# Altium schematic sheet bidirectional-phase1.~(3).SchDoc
size 431 x 279 mm; Date: Not shown in title block; ApprovedBy: Not shown in title block; CheckedBy: Not shown in title block; Author: Not shown in title block; CompanyName: Not shown in title block; Engineer: Not shown in title block; Organization: Not shown in title block; Address1: Not shown in title block; Address2: Not shown in title block; Address3: Not shown in title block; Address4: Not shown in title block; DocumentNumber: 4; Revision: Use project parameter SCH_Rev; SheetNumber: 4; SheetTotal: 6; PageSetup: Record=PageOptions|CenterHorizontal=True|CenterVertical=True|PrintScale=0.96|XCorrection=1.00|YCorrection=1.00|PrintKind=0|BorderSize=5000000|LeftOffset=0|BottomOffset=0|Orientation=2|PaperLength=1000|PaperWidth=1000|Scale=100|PaperSource=15|PrintQuality=600|MediaType=1|DitherType=10|PaperKind=11x17|PrintScaleMode=1
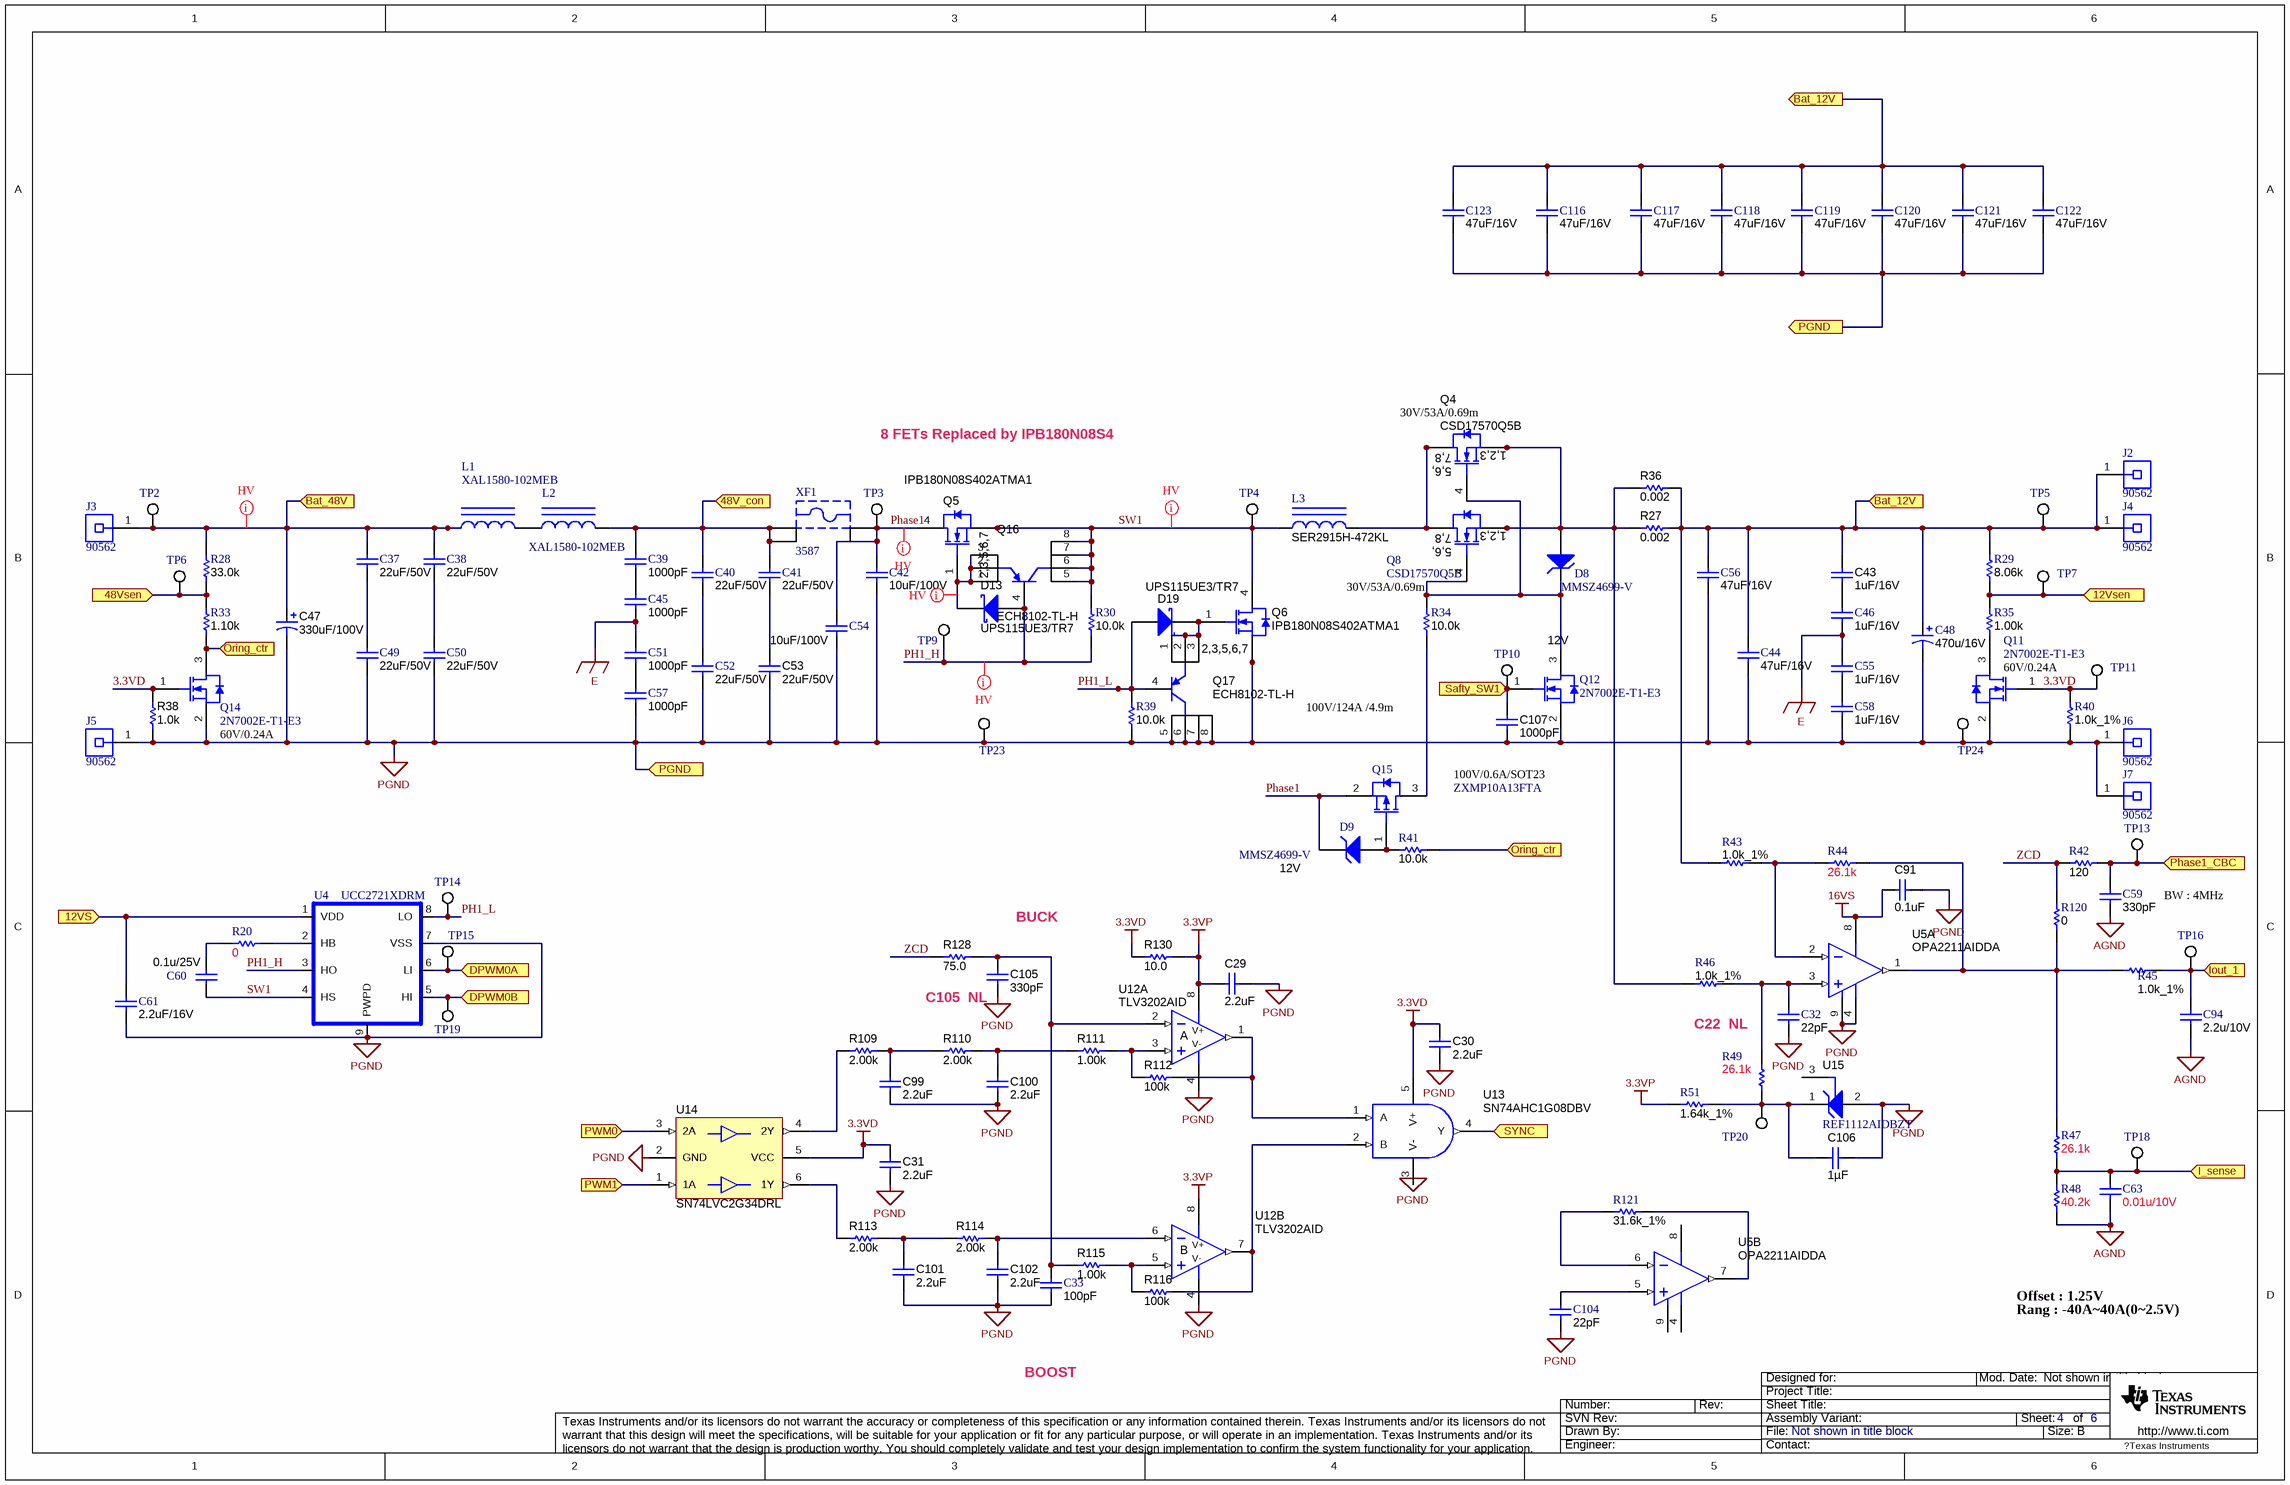
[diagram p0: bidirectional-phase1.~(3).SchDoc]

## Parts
C29  ValueDisplayed: 2.2uF  [0603]  (hidden comment: C0603C225K9PACTU)
C30  ValueDisplayed: 2.2uF  [0603]  (hidden comment: C0603C225K9PACTU)
C31  ValueDisplayed: 2.2uF  [0603]  (hidden comment: C0603C225K9PACTU)
C32  ValueDisplayed: 22pF  [0603]  (hidden comment: 06035A220JAT2A)
C33  ValueDisplayed: 100pF  [0603]  (hidden comment: 06033C101KAT2A)
C37  ValueDisplayed: 22uF/50V  [CKG57N]  (hidden comment: CKG57NX5R1H226M500JH)
C38  ValueDisplayed: 22uF/50V  [CKG57N]  (hidden comment: CKG57NX5R1H226M500JH)
C39  ValueDisplayed: 1000pF  [0603]  (hidden comment: 06031C102JAT2A)
C40  ValueDisplayed: 22uF/50V  [CKG57N]  (hidden comment: CKG57NX5R1H226M500JH)
C41  ValueDisplayed: 22uF/50V  [CKG57N]  (hidden comment: CKG57NX5R1H226M500JH)
C42  ValueDisplayed: 10uF/100V  [2220]  (hidden comment: C5750X7S2A106M)
C43  ValueDisplayed: 1uF/16V  [0805_HV]  (hidden comment: B37941K9105K62)
C44  ValueDisplayed: 47uF/16V  [1210]  (hidden comment: GRM32ER61C476ME15L)
C45  ValueDisplayed: 1000pF  [0603]  (hidden comment: 06031C102JAT2A)
C46  ValueDisplayed: 1uF/16V  [0805_HV]  (hidden comment: B37941K9105K62)
C47  ValueDisplayed: 330uF/100V  [CAPSMT_62_MN0]  (hidden comment: EMVE101GTR331MMN0S)
C48  ValueDisplayed: 470u/16V  [CAPSMT_62_JA0]  (hidden comment: EMVA250ADA471MJA0G)
C49  ValueDisplayed: 22uF/50V  [CKG57N]  (hidden comment: CKG57NX5R1H226M500JH)
C50  ValueDisplayed: 22uF/50V  [CKG57N]  (hidden comment: CKG57NX5R1H226M500JH)
C51  ValueDisplayed: 1000pF  [0603]  (hidden comment: 06031C102JAT2A)
C52  ValueDisplayed: 22uF/50V  [CKG57N]  (hidden comment: CKG57NX5R1H226M500JH)
C53  ValueDisplayed: 22uF/50V  [CKG57N]  (hidden comment: CKG57NX5R1H226M500JH)
C54  ValueDisplayed: 10uF/100V  [2220]  (hidden comment: C5750X7S2A106M)
C55  ValueDisplayed: 1uF/16V  [0805_HV]  (hidden comment: B37941K9105K62)
C56  ValueDisplayed: 47uF/16V  [1210]  (hidden comment: GRM32ER61C476ME15L)
C57  ValueDisplayed: 1000pF  [0603]  (hidden comment: 06031C102JAT2A)
C58  ValueDisplayed: 1uF/16V  [0805_HV]  (hidden comment: B37941K9105K62)
C59  ValueDisplayed: 330pF  [0603]  (hidden comment: 06035A331JAT2A)
C60  ValueDisplayed: 0.1u/25V  [0603]  (hidden comment: 06033C104KAT2A)
C61  ValueDisplayed: 2.2uF/16V  [0805_HV]  (hidden comment: 0805YD225KAT2A)
C63  ValueDisplayed: 0.01u/10V  [0603]  (hidden comment: 06031C103JAT2A)
C91  ValueDisplayed: 0.1uF  [0603]  (hidden comment: 06033C104JAT2A)
C94  ValueDisplayed: 2.2u/10V  [0603]  (hidden comment: C0603C225K8PACTU)
C99  ValueDisplayed: 2.2uF  [0805_HV]  (hidden comment: 0805YD225KAT2A)
C100  ValueDisplayed: 2.2uF  [0805_HV]  (hidden comment: 0805YD225KAT2A)
C101  ValueDisplayed: 2.2uF  [0805_HV]  (hidden comment: 0805YD225KAT2A)
C102  ValueDisplayed: 2.2uF  [0805_HV]  (hidden comment: 0805YD225KAT2A)
C104  ValueDisplayed: 22pF  [0603]  (hidden comment: 06035A220JAT2A)
C105  ValueDisplayed: 330pF  [0603]  (hidden comment: 06031C331JAT2A)
C106  ValueDisplayed: 1µF  [0603_095]  (hidden comment: C0603C105K3RACTU)
C107  ValueDisplayed: 1000pF  [0603]  (hidden comment: C0603X102K5RACTU)
C116  ValueDisplayed: 47uF/16V  [1210]  (hidden comment: GRM32ER61C476ME15L)
C117  ValueDisplayed: 47uF/16V  [1210]  (hidden comment: GRM32ER61C476ME15L)
C118  ValueDisplayed: 47uF/16V  [1210]  (hidden comment: GRM32ER61C476ME15L)
C119  ValueDisplayed: 47uF/16V  [1210]  (hidden comment: GRM32ER61C476ME15L)
C120  ValueDisplayed: 47uF/16V  [1210]  (hidden comment: GRM32ER61C476ME15L)
C121  ValueDisplayed: 47uF/16V  [1210]  (hidden comment: GRM32ER61C476ME15L)
C122  ValueDisplayed: 47uF/16V  [1210]  (hidden comment: GRM32ER61C476ME15L)
C123  ValueDisplayed: 47uF/16V  [1210]  (hidden comment: GRM32ER61C476ME15L)
D8  MMSZ4699-V  value 12V  [SOD-123]
D9  MMSZ4699-V  value 12V  [SOD-123]
D13  UPS115UE3/TR7  [DO-216AA]
D19  UPS115UE3/TR7  [DO-216AA]
J2  90562  [Morris_90562]
J3  90562  [Morris_90562]
J4  90562  [Morris_90562]
J5  90562  [Morris_90562]
J6  90562  [Morris_90562]
J7  90562  [Morris_90562]
L1  XAL1580-102MEB  [XAL1580]
L2  XAL1580-102MEB  [XAL1580]
L3  SER2915H-472KL  [SER2915H]
Q4  CSD17570Q5B  [TRANS_NexFET_Q5B]
Q5  IPB180N08S402ATMA1  [DDPAK-7]
Q6  IPB180N08S402ATMA1  [DDPAK-7]
Q8  CSD17570Q5B  [TRANS_NexFET_Q5B]
Q11  2N7002E-T1-E3  [SOT-23]
Q12  2N7002E-T1-E3  [SOT-23]
Q14  2N7002E-T1-E3  [SOT-23]
Q15  ZXMP10A13FTA  [SOT-23]
Q16  ECH8102-TL-H  [ECH8]
Q17  ECH8102-TL-H  [ECH8]
R20  value 0  [0603]  (hidden comment: MCR03EZPJ000)
R27  ValueDisplayed: 0.002  [2512]  (hidden comment: ERJ-M1WTF2M0U)
R28  ValueDisplayed: 33.0k  [0603]  (hidden comment: CRCW060333K0FKEA)
R29  ValueDisplayed: 8.06k  [0603]  (hidden comment: CRCW06038K06FKEA)
R30  value 10.0k  [0603]  (hidden comment: RG1608P-103-B-T5)
R33  ValueDisplayed: 1.10k  [0603]  (hidden comment: RC0603FR-071K1L)
R34  ValueDisplayed: 10.0k  [0603]  (hidden comment: CRCW060310K0FKEA)
R35  ValueDisplayed: 1.00k  [0603]  (hidden comment: CRCW06031K00FKEA)
R36  ValueDisplayed: 0.002  [2512]  (hidden comment: ERJ-M1WTF2M0U)
R38  value 1.0k  [0603]  (hidden comment: CRCW06031K00JNEA)
R39  value 10.0k  [0603]  (hidden comment: RG1608P-103-B-T5)
R40  value 1.0k_1%  [0603]  (hidden comment: CRCW06031K00JNEA)
R41  ValueDisplayed: 10.0k  [0603]  (hidden comment: CRCW060310K0FKEA)
R42  ValueDisplayed: 120  [0603]  (hidden comment: CRCW0603120RJNEA)
R43  value 1.0k_1%  [0603]  (hidden comment: CRCW06031K00JNEA)
R44  value 26.1k  [0603]  (hidden comment: CRCW060326K1FKEA)
R45  value 1.0k_1%  [0603]  (hidden comment: CRCW06031K00JNEA)
R46  value 1.0k_1%  [0603]  (hidden comment: CRCW06031K00JNEA)
R47  value 26.1k  [0603]  (hidden comment: CRCW060326K1FKEA)
R48  value 40.2k  [0603]  (hidden comment: CRCW060340K2FKEA)
R49  value 26.1k  [0603]  (hidden comment: CRCW060326K1FKEA)
R51  value 1.64k_1%  [0603]  (hidden comment: CRCW06031K65FKEA)
R109  value 2.00k  [0603]  (hidden comment: CRCW06032K00FKEA)
R110  value 2.00k  [0603]  (hidden comment: CRCW06032K00FKEA)
R111  value 1.00k  [0603]  (hidden comment: CRCW06031K00FKEA)
R112  ValueDisplayed: 100k  [0603]  (hidden comment: CRCW0603100KJNEA)
R113  value 2.00k  [0603]  (hidden comment: CRCW06032K00FKEA)
R114  value 2.00k  [0603]  (hidden comment: CRCW06032K00FKEA)
R115  value 1.00k  [0603]  (hidden comment: CRCW06031K00FKEA)
R116  ValueDisplayed: 100k  [0603]  (hidden comment: CRCW0603100KJNEA)
R120  value 0  [0603]  (hidden comment: ERJ-3GEY0R00V)
R121  value 31.6k_1%  [0603]  (hidden comment: CRCW060331K6FKEA)
R128  ValueDisplayed: 75.0  [0603]  (hidden comment: CRCW060375R0FKEA)
R130  value 10.0  [0603]  (hidden comment: CRCW060310R0FKEA)
TP2  5002  [Keystone5002]  (value not drawn)
TP3  5016  [Testpoint_Keystone_Compact]  (value not drawn)
TP4  5002  [Keystone5002]  (value not drawn)
TP5  5002  [Keystone5002]  (value not drawn)
TP6  5002  [Keystone5002]  (value not drawn)
TP7  5002  [Keystone5002]  (value not drawn)
TP9  5002  [Keystone5002]  (value not drawn)
TP10  5002  [Keystone5002]  (value not drawn)
TP11  5002  [Keystone5002]  (value not drawn)
TP13  5002  [Keystone5002]  (value not drawn)
TP14  5002  [Keystone5002]  (value not drawn)
TP15  5002  [Keystone5002]  (value not drawn)
TP16  5002  [Keystone5002]  (value not drawn)
TP18  5002  [Keystone5002]  (value not drawn)
TP19  5002  [Keystone5002]  (value not drawn)
TP20  5002  [Keystone5002]  (value not drawn)
TP23  5002  [Keystone5002]  (value not drawn)
TP24  5002  [Keystone5002]  (value not drawn)
U4  UCC2721XDRM  [DRM0008A]
U5  OPA2211AIDDA  [DDA0008C_N]  (parts A,B of 2)
U12  TLV3202AID  [D0008A_L]  (parts A,B of 2)
U13  SN74AHC1G08DBV  [DBV0005A_N]
U14  SN74LVC2G34DRL  [DRL0006A_N]
U15  REF1112AIDBZT  [DBZ0003A_N]
XF1  3587  [KEYSTONE_3587]

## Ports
12VS, 12Vsen, 48V_con, 48Vsen, Bat_12V, Bat_48V, DPWM0A, DPWM0B, I_sense, Iout_1, Oring_ctr, PGND, Phase1_CBC, PWM0, PWM1, Safty_SW1, SYNC

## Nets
3.3VD: C30.1 C31.2 Q11.1(G) Q14.1(G) R38.2 R40.2 R130.2 TP11.1 U13.5(V+) U14.5(VCC)
3.3VP: C29.2 R51.1 R130.1 U12.8(V+)
16VS: C91.1 U5.8(V+)
AGND: C59.2 C63.2 C94.2 R48.1
E: C45.2 C46.2 C51.1 C55.1
PGND: C29.1 C30.2 C31.1 C32.2 C33.2 C42.2 C44.2 C47.2(-) C48.2(-) C49.2 C50.2 C52.2 C53.2 C54.2 C56.2 C57.2 C58.2 C61.2 C91.2 C99.2 C100.2 C101.2 C102.2 C104.2 C105.2 C106.1 C107.2 C116.2 C117.2 C118.2 C119.2 C120.2 C121.2 C122.2 C123.2 J5.1 J6.1 J7.1 Q6.2(S) Q6.3(S) Q6.5(S) Q6.6(S) Q6.7(S) Q11.2(S) Q12.2(S) Q14.2(S) Q17.5(C) Q17.6(C) Q17.7(C) Q17.8(C) R38.1 R39.1 R40.1 TP23.1 TP24.1 U4.7(VSS) U4.9(PWPD) U5.4(V-) U5.9(EP) U12.4(V-) U14.2(GND) U15.2(GND) ; port PGND
12VS: C61.1 U4.1(VDD) ; port 12VS
12Vsen: R29.1 R35.2 TP7.1 ; port 12Vsen
48V_con: C39.1 C40.1 C41.1 L2.2 XF1.1 XF1.2 ; port 48V_con
48Vsen: R28.1 R33.2 TP6.1 ; port 48Vsen
Bat_12V: C43.1 C44.1 C48.1(+) C56.1 C116.1 C117.1 C118.1 C119.1 C120.1 C121.1 C122.1 C123.1 J2.1 J4.1 R27.2 R29.2 R36.2 R43.1 TP5.1 ; port Bat_12V
Bat_48V: C37.1 C38.1 C47.1(+) J3.1 L1.1 R28.2 TP2.1 ; port Bat_48V
DPWM0A: TP15.1 U4.6(LI) ; port DPWM0A
DPWM0B: TP19.1 U4.5(HI) ; port DPWM0B
I_sense: C63.1 R47.1 R48.2 TP18.1 ; port I_sense
Iout_1: C94.1 R45.2 TP16.1 ; port Iout_1
Oring_ctr: Q14.3(D) R33.1 R41.1 ; port Oring_ctr
PH1_H: D13.2(A) Q16.4(B) R30.1 TP9.1 U4.3(HO)
PH1_L: D19.2(A) Q17.4(B) R39.2 TP14.1 U4.8(LO)
Phase1: C42.1 C54.1 D9.1(K) Q5.4(D) Q15.2(S) TP3.1 XF1.3 XF1.4
Phase1_CBC: C59.1 R42.2 TP13.1 ; port Phase1_CBC
PWM0: U14.3(2A) ; port PWM0
PWM1: U14.1(1A) ; port PWM1
Safty_SW1: C107.1 Q12.1(G) TP10.1 ; port Safty_SW1
SW1: C60.2 L3.1 Q5.2(S) Q5.3(S) Q5.5(S) Q5.6(S) Q5.7(S) Q6.4(D) Q16.5(C) Q16.6(C) Q16.7(C) Q16.8(C) R30.2 TP4.1 U4.4(HS)
SYNC: U13.4(Y) ; port SYNC
ZCD: R42.1 R120.2 R128.1
NetC32_1: C32.1 R46.2 R49.2 U5.3(IN_A+)
NetC33_1: C33.1 C105.1 R115.1 R128.2 U12.2(IN-)
NetC37_2: C37.2 C49.1
NetC38_2: C38.2 C50.1
NetC39_2: C39.2 C45.1
NetC40_2: C40.2 C52.1
NetC41_2: C41.2 C53.1
NetC43_2: C43.2 C46.1
NetC51_2: C51.2 C57.1
NetC55_2: C55.2 C58.1
NetC60_1: C60.1 R20.1
NetC99_1: C99.1 R109.2 R110.1
NetC100_1: C100.1 R110.2 R111.1
NetC101_1: C101.1 R113.2 R114.1
NetC102_1: C102.1 R114.2 U12.6(IN-)
NetC104_1: C104.1 U5.5(IN_B+)
NetC106_2: C106.2 R49.1 R51.2 TP20.1 U15.1(VO)
NetD8_1: D8.1(K) Q4.4(G) Q8.4(G) Q12.3(D) R34.2
NetD8_2: D8.2(A) Q4.1(S) Q4.2(S) Q4.3(S) Q8.1(S) Q8.2(S) Q8.3(S) R27.1 R36.1 R46.1
NetD9_2: D9.2(A) Q15.1(G) R41.2
NetD13_1: D13.1(K) Q5.1(G) Q16.1(E) Q16.2(E) Q16.3(E)
NetD19_1: D19.1(K) Q6.1(G) Q17.1(E) Q17.2(E) Q17.3(E)
NetL1_2: L1.2 L2.1
NetL3_2: L3.2 Q4.5(D) Q4.6(D) Q4.7(D) Q4.8(D) Q8.5(D) Q8.6(D) Q8.7(D) Q8.8(D)
NetQ11_3: Q11.3(D) R35.1
NetQ15_3: Q15.3(D) R34.1
NetR20_2: R20.2 U4.2(HB)
NetR43_2: R43.2 R44.1 U5.2(IN_A-)
NetR44_2: R44.2 R45.1 R47.2 R120.1 U5.1(OUT_A)
NetR109_1: R109.1 U14.4(2Y)
NetR111_2: R111.2 R112.2 U12.3(IN+)
NetR112_1: R112.1 U12.1(OUT) U13.1(A)
NetR113_1: R113.1 U14.6(1Y)
NetR115_2: R115.2 R116.2 U12.5(IN+)
NetR116_1: R116.1 U12.7(OUT) U13.2(B)
NetR121_1: R121.1 U5.6(IN_B-)
NetR121_2: R121.2 U5.7(OUT_B)

Not connected (* = marked no-connect by the designer): U13 3(V-); U15 3(NC)

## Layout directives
net class HV: Bat_48V, NetD13_1, PH1_H, Phase1, SW1

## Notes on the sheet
- 8 FETs Replaced by IPB180N08S4
- (near Q4) 30V/53A/0.69m
- (near R34) 30V/53A/0.69m
- (near Q11) 60V/0.24A
- (near Q14) 60V/0.24A
- 100V/124A /4.9m
- 100V/0.6A/SOT23
- BW : 4MHz
- BUCK
- (near C105) C105  NL
- C22  NL
- Offset : 1.25V
- BOOST
- Rang : -40A~40A(0|.5V)
- Labels drawn without touching a wire or pin: PGND

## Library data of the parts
C29-C31 = C0603C225K9PACTU: CAP, CERM, 2.2uF, 6.3V, +/-10%, X5R, 0603; Manufacturer: Kemet; Polarized: N; CompType: Capacitor; U/M: EA; Cap_F: 0.0000022; Tolerance_%: 10; Value1: Unknown; VDC_V: 6.3; TaMin_C: -55; TaMax_C: 85
C32 C104 = 06035A220JAT2A: CAP, CERM, 22pF, 50V, +/-5%, C0G/NP0, 0603; Manufacturer: AVX; Polarized: N; CompType: Capacitor; U/M: EA; Cap_F: 0.000000000022; Tolerance_%: 5; ESR_Ohm: 0.259; Value1: 0.259 ohm; VDC_V: 50; TaMin_C: -55; TaMax_C: 125
C33 = 06033C101KAT2A: CAP, CERM, 100pF, 25V, +/-10%, X7R, 0603; Manufacturer: AVX; Polarized: N; CompType: Capacitor; U/M: EA; Cap_F: 0.0000000001; Tolerance_%: 10; Value1: Unknown; VDC_V: 25; TaMin_C: -55; TaMax_C: 125
C37 C38 C40 C41 C49 C50 C52 C53 = CKG57NX5R1H226M500JH: CAP, CERM, 22uF, 50V, +/-20%, X5R, 6x5x5mm; Manufacturer: TDK; Polarized: N; CompType: Capacitor; U/M: EA; Cap_F: 0.000022; Tolerance_%: 20; Value1: Unknown; VDC_V: 50; TaMin_C: -55; TaMax_C: 85; Cap_Case: 2220
C39 C45 C51 C57 = 06031C102JAT2A: CAP, CERM, 1000pF, 100V, +/-5%, X7R, 0603; Manufacturer: AVX; Polarized: N; CompType: Capacitor; U/M: EA; Cap_F: 0.000000001; Tolerance_%: 5; ESR_Ohm: 0.276; Value1: 0.276 ohm; VDC_V: 100; TaMin_C: -55; TaMax_C: 125
C42 C54 = C5750X7S2A106M: CAP, CERM, 10uF, 100V, +/-20%, X7S, 2220; Manufacturer: TDK; Polarized: N; CompType: Capacitor; U/M: EA; Cap_F: 0.00001; Tolerance_%: 20; ESR_Ohm: 0.005; Value1: 0.005 ohm; VDC_V: 100; IRMS_A: 6.45; TaMin_C: -55; TaMax_C: 125
C43 C46 C55 C58 = B37941K9105K62: CAP, CERM, 1uF, 16V, +/-10%, X7R, 0805; Manufacturer: EPCOS Inc; Polarized: N; CompType: Capacitor; U/M: EA; Cap_F: 0.000001; Tolerance_%: 10; Value1: Unknown; VDC_V: 16; TaMin_C: -55; TaMax_C: 125; Cap_Case: 0805
C44 C56 C116-C123 = GRM32ER61C476ME15L: CAP, CERM, 47uF, 16V, +/-20%, X5R, 1210; Manufacturer: MuRata; Polarized: N; CompType: Capacitor; U/M: EA; Cap_F: 0.000047; Tolerance_%: 20; ESR_Ohm: 0.002; Value1: 0.002 ohm; VDC_V: 16; TaMin_C: -55; TaMax_C: 85
C47 = EMVE101GTR331MMN0S: CAP, AL, 330uF, 100V, +/-20%,  ohm, SMD; Manufacturer: Nippon Chemi-Con; Polarized: Y; CompType: Capacitor; U/M: EA; Cap_F: 0.00033; Tolerance_%: 20; Value1: Unknown; VDC_V: 100; IRMS_A: 0.98; TaMin_C: -40; TaMax_C: 105; Cap_Case: MN0
C48 = EMVA250ADA471MJA0G: CAP, AL, 470uF, 25V, +/-20%,  ohm, SMD; Manufacturer: Nippon Chemi-Con; Polarized: Y; CompType: Capacitor; U/M: EA; Cap_F: 0.00047; Tolerance_%: 20; Value1: Unknown; VDC_V: 25; IRMS_A: 0.4; TaMin_C: -40; TaMax_C: 85; Cap_Case: JA0
C59 = 06035A331JAT2A: CAP, CERM, 330pF, 50V, +/-5%, C0G/NP0, 0603; Manufacturer: AVX; Polarized: N; CompType: Capacitor; U/M: EA; Cap_F: 0.00000000033; Tolerance_%: 5; ESR_Ohm: 0.071; Value1: 0.071 ohm; VDC_V: 50; TaMin_C: -55; TaMax_C: 125
C60 = 06033C104KAT2A: CAP, CERM, 0.1uF, 25V, +/-10%, X7R, 0603; Manufacturer: AVX; Polarized: N; CompType: Capacitor; U/M: EA; Cap_F: 0.0000001; Tolerance_%: 10; ESR_Ohm: 0.05; Value1: 0.05 ohm; VDC_V: 25; TaMin_C: -55; TaMax_C: 125
C61 C99-C102 = 0805YD225KAT2A: CAP, CERM, 2.2uF, 16V, +/-10%, X5R, 0805; Manufacturer: AVX; Polarized: N; CompType: Capacitor; U/M: EA; Cap_F: 0.0000022; Tolerance_%: 10; ESR_Ohm: 0.009; Value1: 0.009 ohm; VDC_V: 16; TaMin_C: -55; TaMax_C: 85; Cap_Case: 0805
C63 = 06031C103JAT2A: CAP, CERM, 0.01uF, 100V, +/-5%, X7R, 0603; Manufacturer: AVX; Polarized: N; CompType: Capacitor; U/M: EA; Cap_F: 0.00000001; Tolerance_%: 5; ESR_Ohm: 0.098; Value1: 0.098 ohm; VDC_V: 100; TaMin_C: -55; TaMax_C: 125
C91 = 06033C104JAT2A: CAP, CERM, 0.1uF, 25V, +/-5%, X7R, 0603; Manufacturer: AVX; Polarized: N; CompType: Capacitor; U/M: EA; Cap_F: 0.0000001; Tolerance_%: 5; ESR_Ohm: 0.05; Value1: 0.05 ohm; VDC_V: 25; TaMin_C: -55; TaMax_C: 125
C94 = C0603C225K8PACTU: CAP, CERM, 2.2uF, 10V, +/-10%, X5R, 0603; Manufacturer: Kemet; Polarized: N; CompType: Capacitor; U/M: EA; Cap_F: 0.0000022; Tolerance_%: 10; Value1: Unknown; TaMin_C: -55; TaMax_C: 85
C105 = 06031C331JAT2A: CAP, CERM, 330pF, 100V, +/-5%, X7R, 0603; Manufacturer: AVX; Polarized: N; CompType: Capacitor; U/M: EA; Cap_F: 0.00000000033; Tolerance_%: 5; ESR_Ohm: 0.472; Value1: 0.472 ohm; VDC_V: 100; TaMin_C: -55; TaMax_C: 125
C106 = C0603C105K3RACTU: CAP, CERM, 1 µF, 25 V, +/- 10%, X7R, 0603_095; Manufacturer: Kemet; Polarized: N; CompType: Capacitor; Value: 1uF; U/M: EA; Cap_F: 0.000001; Tolerance_%: 10; Value1: Unknown; VDC_V: 25; Value2: 25V; TaMin_C: -55; TaMax_C: 125; Cap_Case: 0603
C107 = C0603X102K5RACTU: CAP, CERM, 1000 pF, 50 V, +/- 10%, X7R, 0603; Manufacturer: Kemet; Polarized: N; CompType: Capacitor; Value: 1000pF; U/M: EA; Cap_F: 0.000000001; Tolerance_%: 10; Value1: Unknown; VDC_V: 50; Value2: 50V; TaMin_C: -55; TaMax_C: 125
D8 D9 = MMSZ4699-V: Diode, Zener, 12V, 500mW, SOD-123; Manufacturer: Vishay-Semiconductor; SymbolCreator: a0412235; U/M: EA; Power_W: 0.5; Vz_V: 12; Value1: 0.5W; RJA_CperW: 67
D13 D19 = UPS115UE3/TR7: Diode, Schottky, 15 V, 1 A, DO-216-AA; Manufacturer: Microsemi; U/M: EA; Vf_V: 0.31; Value: 15V; Value1: 1A; Value2: 0.31V; Io_A: 1; Vr_V: 15; TJmax_C: 100
J2-J7 = 90562: Connector Lug, wire range #6 - 4/0, 600V; Manufacturer: Morris Products; SymbolCreator: a0799628; CompType: Receptacle; U/M: EA
L1 L2 = XAL1580-102MEB: Inductor, Shielded, Composite, 1uH, 57.5A, 0.000929 ohm, SMD; Manufacturer: Coilcraft; Ind_H: 1.0E-6; ValueDisplayed: 1µH; Imax_A: 57.5; Irms: 57.5A @ 40C rise; Isat: 73.5A @ 0.7% inductance drop; U/M: EA
L3 = SER2915H-472KL: Inductor, Shielded E Core, Ferrite, 4.7 µH, 30 A, 0.00186 ohm, SMD; Manufacturer: Coilcraft; Value: 4.7uH; Ind_H: 4.7E-6; ValueDisplayed: 4.7µH; Imax_A: 30; Irms: 30A @ 40C rise; Isat: 50.1A @ 30% inductance drop; Value2: 30A
Q4 Q8 = CSD17570Q5B: MOSFET, N-CH, 30V, 51A, SON 5x6mm; Manufacturer: Texas Instruments; Alternate Manufacturer: None; U/M: EA; ChType: N; VdsMax_V: 30; Value1: 0.0076 ohm; Rdson45_Ohm: 0.0076; Value2: 97 nC; QgTyp_nC: 97; Vgs_V: 20; IdsMax_A: 51
Q5 Q6 = IPB180N08S402ATMA1: MOSFET, N-CH, 80 V, 180 A, DDPAK-7; Manufacturer: Infineon Technologies; Alternate Manufacturer: None; SymbolCreator: a0412235; U/M: EA; ChType: N; Value: 80V; VdsMax_V: 80; Value1: ? ohm; Value2: 128 nC; QgTyp_nC: 128; Vgs_V: 20; IdsMax_A: 180
Q11 Q12 Q14 = 2N7002E-T1-E3: MOSFET, N-CH, 60V, 0.24A, SOT-23; Manufacturer: Vishay-Siliconix; Alternate Manufacturer: None; U/M: EA; ChType: N; VdsMax_V: 60; Value1: 1.8 ohm; Rdson45_Ohm: 1.8; Value2: 0.4 nC; QgTyp_nC: 0.4; Vgs_V: 20; IdsMax_A: 0.24
Q15 = ZXMP10A13FTA: MOSFET, P-CH, -100V, -0.6A, SOT-23; Manufacturer: Diodes Inc.; Alternate Manufacturer: None; U/M: EA; ChType: P; VdsMax_V: -100; Value1: 1 ohm; Rdson45_Ohm: 1; Value2: 3.5 nC; QgTyp_nC: 3.5; Vgs_V: -4; IdsMax_A: -0.6
Q16 Q17 = ECH8102-TL-H, ON Semiconductor: Transistor, PNP, 30 V, 12 A, SMD-8; CompType: BJT; PNP: 1; NPN: 0; Vceo_V: 30; Vcesat1_V: 0.08; Value: 30 V; IcRated_A: 12; Value1: 12 A; HfeMax: 560; TaMin_C: -55; TaMax_C: 150; U/M: EA
R20 = MCR03EZPJ000: RES, 0 ohm, 5%, 0.1W, 0603; Manufacturer: Rohm; CompType: Resistor; Value_Code: 0000; Tolerance_%: 5; Power_W: 0.1; VDC_V: 50; TempCo: 400 ppm/C; EIA_Code: E24; U/M: EA
R27 R36 = ERJ-M1WTF2M0U: RES, 0.002, 1%, 1 W, 2512; Manufacturer: Panasonic; CompType: Resistor; Value: 0.002; Value_Code: 2L000; Tolerance_%: 1; Value2: 1W; TempCo: ppm/C; U/M: EA
R28 = CRCW060333K0FKEA: RES, 33.0 k, 1%, 0.1 W, 0603; Manufacturer: Vishay-Dale; CompType: Resistor; Value: 33.0k; Res_ohm: 33000; Value_Code: 33k0; Tolerance_%: 1; Power_W: 0.1; Value2: 0.1W; VDC_V: 75; TempCo: 100 ppm/C; U/M: EA
R29 = CRCW06038K06FKEA: RES, 8.06 k, 1%, 0.1 W, 0603; Manufacturer: Vishay-Dale; CompType: Resistor; Value: 8.06k; Res_ohm: 8060; Value_Code: 8k06; Tolerance_%: 1; Power_W: 0.1; Value2: 0.1W; VDC_V: 75; TempCo: 100 ppm/C; EIA_Code: E96; U/M: EA
R30 R39 = RG1608P-103-B-T5: RES, 10.0k ohm, 0.1%, 0.1W, 0603; Manufacturer: Susumu Co Ltd; CompType: Resistor; Res_ohm: 10000; Value_Code: 10k0; Tolerance_%: 0.1; VDC_V: 75; TempCo: 25 ppm/C; EIA_Code: E192; U/M: EA
R33 = RC0603FR-071K1L: RES, 1.10 k, 1%, 0.1 W, 0603; Manufacturer: Yageo America; CompType: Resistor; Value: 1.10k; Res_ohm: 1100; Value_Code: 1k10; Tolerance_%: 1; Power_W: 0.1; Value2: 0.1W; VDC_V: 150; TempCo: 200 ppm/C; EIA_Code: E96; U/M: EA
R34 R41 = CRCW060310K0FKEA: RES, 10.0 k, 1%, 0.1 W, 0603; Manufacturer: Vishay-Dale; CompType: Resistor; Value: 10.0k; Res_ohm: 10000; Value_Code: 10k0; Tolerance_%: 1; Power_W: 0.1; Value2: 0.1W; VDC_V: 75; TempCo: 100 ppm/C; EIA_Code: E96; U/M: EA
R35 = CRCW06031K00FKEA: RES, 1.00 k, 1%, 0.1 W, 0603; Manufacturer: Vishay-Dale; CompType: Resistor; Value: 1.00k; Res_ohm: 1000; Value_Code: 1k00; Tolerance_%: 1; Power_W: 0.1; Value2: 0.1W; VDC_V: 75; TempCo: 100 ppm/C; EIA_Code: E96; U/M: EA
R38 R40 R43 R45 R46 = CRCW06031K00JNEA: RES, 1.0k ohm, 5%, 0.1W, 0603; Manufacturer: Vishay-Dale; CompType: Resistor; Res_ohm: 1000; Value_Code: 1k00; Tolerance_%: 5; Power_W: 0.1; VDC_V: 75; TempCo: 200 ppm/C; EIA_Code: E24; U/M: EA
R42 = CRCW0603120RJNEA: RES, 120, 5%, 0.1 W, 0603; Manufacturer: Vishay-Dale; CompType: Resistor; Value: 120; Value_Code: 120R; Tolerance_%: 5; Power_W: 0.1; Value2: 0.1W; VDC_V: 75; TempCo: 200 ppm/C; EIA_Code: E24; U/M: EA
R44 R47 R49 = CRCW060326K1FKEA: RES, 26.1k ohm, 1%, 0.1W, 0603; Manufacturer: Vishay-Dale; CompType: Resistor; Res_ohm: 26100; Value_Code: 26k1; Tolerance_%: 1; Power_W: 0.1; VDC_V: 75; TempCo: 100 ppm/C; EIA_Code: E96; U/M: EA
R48 = CRCW060340K2FKEA: RES, 40.2k ohm, 1%, 0.1W, 0603; Manufacturer: Vishay-Dale; CompType: Resistor; Res_ohm: 40200; Value_Code: 40k2; Tolerance_%: 1; Power_W: 0.1; VDC_V: 75; TempCo: 100 ppm/C; EIA_Code: E96; U/M: EA
R51 = CRCW06031K65FKEA: RES, 1.65k ohm, 1%, 0.1W, 0603; Manufacturer: Vishay-Dale; CompType: Resistor; Res_ohm: 1650; Value_Code: 1k65; Tolerance_%: 1; Power_W: 0.1; VDC_V: 75; TempCo: 100 ppm/C; EIA_Code: E96; U/M: EA
R109 R110 R113 R114 = CRCW06032K00FKEA: RES, 2.00k ohm, 1%, 0.1W, 0603; Manufacturer: Vishay-Dale; CompType: Resistor; Res_ohm: 2000; Value_Code: 2k00; Tolerance_%: 1; Power_W: 0.1; VDC_V: 75; TempCo: 100 ppm/C; EIA_Code: E96; U/M: EA
R111 R115 = CRCW06031K00FKEA: RES, 1.00k ohm, 1%, 0.1W, 0603; Manufacturer: Vishay-Dale; CompType: Resistor; Res_ohm: 1000; Value_Code: 1k00; Tolerance_%: 1; Power_W: 0.1; VDC_V: 75; TempCo: 100 ppm/C; EIA_Code: E96; U/M: EA
R112 R116 = CRCW0603100KJNEA: RES, 100 k, 5%, 0.1 W, 0603; Manufacturer: Vishay-Dale; CompType: Resistor; Value: 100k; Res_ohm: 100000; Tolerance_%: 5; Power_W: 0.1; Value2: 0.1W; VDC_V: 75; TempCo: 200 ppm/C; EIA_Code: E24; U/M: EA
R120 = ERJ-3GEY0R00V: RES, 0 ohm, 5%, 0.1W, 0603; Manufacturer: Panasonic; CompType: Resistor; Value_Code: 0000; Tolerance_%: 5; Power_W: 0.1; VDC_V: 50; TempCo: 600 ppm/C; EIA_Code: E24; U/M: EA
R121 = CRCW060331K6FKEA: RES, 31.6k ohm, 1%, 0.1W, 0603; Manufacturer: Vishay-Dale; CompType: Resistor; Res_ohm: 31600; Value_Code: 31k6; Tolerance_%: 1; Power_W: 0.1; VDC_V: 75; TempCo: 100 ppm/C; EIA_Code: E96; U/M: EA
R128 = CRCW060375R0FKEA: RES, 75.0, 1%, 0.1 W, 0603; Manufacturer: Vishay-Dale; CompType: Resistor; Value: 75.0; Res_ohm: 75; Value_Code: 75R0; Tolerance_%: 1; Power_W: 0.1; Value2: 0.1W; TempCo: 100 ppm/C; EIA_Code: E96; U/M: EA
R130 = CRCW060310R0FKEA: RES, 10.0 ohm, 1%, 0.1W, 0603; Manufacturer: Vishay-Dale; CompType: Resistor; Res_ohm: 10; Value_Code: 10R0; Tolerance_%: 1; Power_W: 0.1; VDC_V: 75; TempCo: 100 ppm/C; EIA_Code: E96; U/M: EA
TP2 TP4-TP7 TP9-TP11 TP13-TP16 TP18-TP20 TP23 TP24 = 5002: Test Point, Miniature, White, TH; Manufacturer: Keystone; CompType: Test Point Loop; U/M: EA
TP3 = 5016: Test Point, Compact, SMT; Manufacturer: Keystone; CompType: Test Point Loop; U/M: EA
U4 = UCC2721XDRM: IC, 120V Boot, 4A Peak, High Frequency High-Side Low-Side Driver; Manufacturer: TI; Alternate Manufacturer: None; Area: 41800
U5 = OPA2211AIDDA: 1.1 nV/rtHz Noise, Low Power, Precision Operational Amplifier, 4.5 to 36 V, -40 to 125 degC, 8-pin SOP (DDA0008C), Green (RoHS & no Sb/Br); Manufacturer: Texas Instruments; Alternate PartNumber: Equivalent; CMRR(Min)(dB): 114; GBW(Typ)(MHz): 45; IIB(Max)(pA): 175000; Iq per channel(Max)(mA): 4.5; Number of Channels: 2; Offset Drift(Typ)(uV/C): 0.35; Packing: TUBE; Rating: Catalog; Slew Rate(Typ)(V/us): 27; Sub Family: High Supply Voltage Amplifier (>=30V), Low Noise Amp (<=10nV/rtHz), Low Offset Voltage Amplifier (<=500uV), Precision Amplifier; Total Supply Voltage(Max)(+5V is 5, +/-5V is 10): 36; Vio (25C)(Max)(mV): 0.15
U12 = TLV3202AID: 40-ns, microPOWER, Push-Pull Output Comparators, D0008A; Alternate Manufacturer: None; Manufacturer: Texas Instruments; CompType: IC; U/M: EA
U13 = SN74AHC1G08DBV: Single 2-Input Positive-AND Gate, DBV0005A; Manufacturer: Texas Instruments; CompType: IC; U/M: EA
U14 = SN74LVC2G34DRL: DUAL BUFFER GATE, DRL0006A; Alternate Manufacturer: None; Manufacturer: Texas Instruments; SymbolCreator: a0411947; CompType: IC; U/M: EA
U15 = REF1112AIDBZT: 1 uA Shunt Voltage Reference, 1.25 V, 10 ppm / degC, 5 mA, -40 to 85 degC, 3-pin SOT-23 (DBZ), Green (RoHS & no Sb/Br); Manufacturer: Texas Instruments; Alternate PartNumber: Equivalent; Initial Accuracy @ 25/deg C(%): 0.2; Iout/Iz(Max)(mA): 5; Min Iz for Regulation(uA): 1.2; Rating: Catalog; Temp Coeff(Max)(ppm/ degree C): 50; Temp Coeff(Typ)(ppm/ degree C): 10; VO(V): 1.25
XF1 = 3587: FuseHolder; Manufacturer: Keystone; SymbolCreator: a0799628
